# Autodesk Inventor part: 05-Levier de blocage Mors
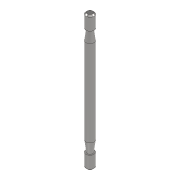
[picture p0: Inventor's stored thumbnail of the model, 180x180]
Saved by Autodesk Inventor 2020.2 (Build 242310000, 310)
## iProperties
Created: 2022-02
Part Number: 05-Levier de blocage Mors
Material: Acier, alliage
Document SubType Name: Modeling
Designer: Philippe
Density: 7.73 g/cm^3
Appearance: Semi-poli
Author: Philippe
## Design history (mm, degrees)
derived "Base-Etau.ipt"
feature "05-Levier de blocage Mors::Base-Etau.ipt" dims "d0" = 10
tag "FonctionRepérage1"
node "Solide1"
